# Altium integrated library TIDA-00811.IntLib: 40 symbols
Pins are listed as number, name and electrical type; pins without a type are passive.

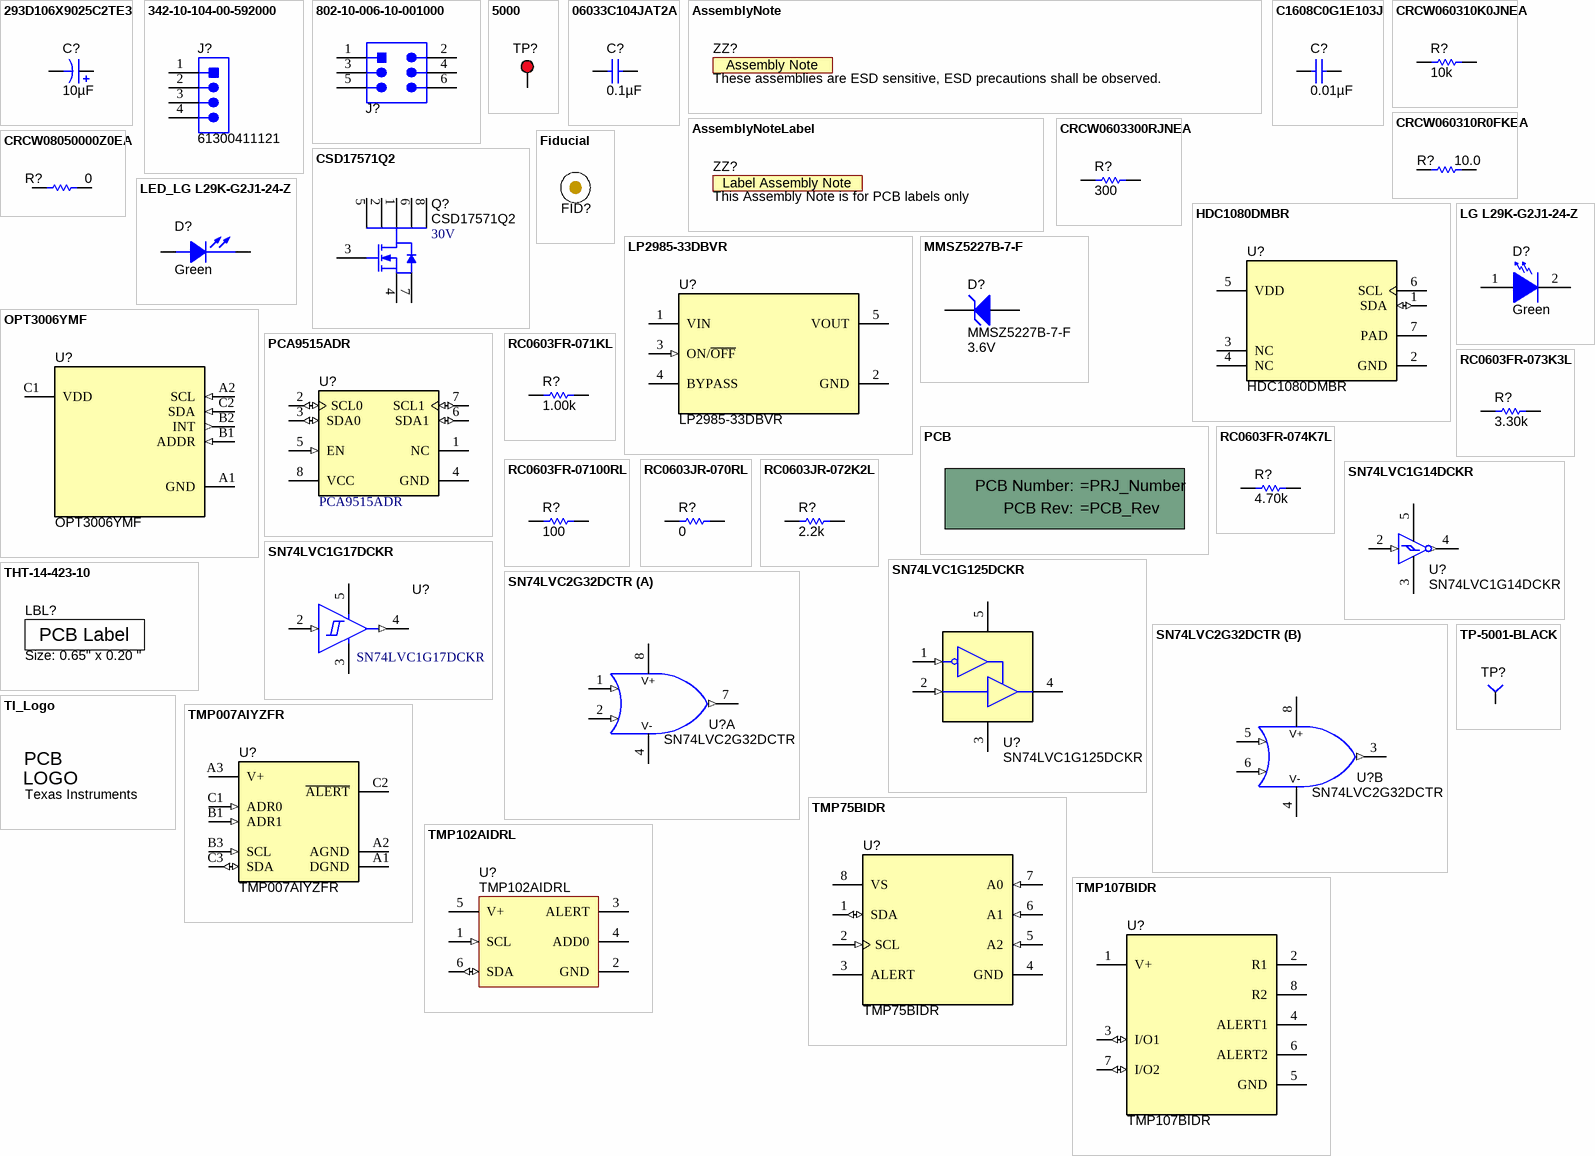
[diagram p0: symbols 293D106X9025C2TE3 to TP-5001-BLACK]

## 293D106X9025C2TE3
designator C?  ValueDisplayed: 10µF  (hidden comment: 293D106X9025C2TE3)
CAP, TA, 10 µF, 25 V, +/- 10%, 1.5 ohm, SMD; Manufacturer: Vishay-Sprague; Polarized: Y; CompType: Capacitor; Value: 10uF; U/M: EA; Cap_F: 0.00001; Tolerance_%: 10; Value1: 1.5 ohm; VDC_V: 25; Value2: 25V; ESR_ohm: 1.5; IRMS_A: 0.27; TaMin_C: -55; TaMax_C: 125; Cap_Case: C; AEC Category: Q200
signal-integrity model Cap
simulation model Cap
footprint 6032-28 (Medium Density IPC based on Vishay Sprague 293D datasheet.)
pins: 1 +, 2 -

## 342-10-104-00-592000
designator J?, comment 61300411121
Header, 2.54mm, 4x1, Gold, TH; Manufacturer: Mill-Max; SymbolCreator: a0412235; Pitch_mm: 2.54; Gender: Male; Shrouded: N; Row_Count: 1
footprint Mill-Max_342-xx-104-00-592000
pins: 1, 2, 3, 4

## 802-10-006-10-001000
designator J?, comment 61300621121  (value not drawn)
Header, 2.54 mm, 3x2, Gold, TH; Manufacturer: Mill-Max; SymbolCreator: a0412235; Pitch_mm: 2.54; Gender: Male; Shrouded: N; Row_Count: 2
footprint Mill-Max_802-10-006-10-001000
pins: 1, 2, 3, 4, 5, 6

## 5000
designator TP?  (value not drawn)
Test Point, Miniature, Red, TH; Manufacturer: Keystone; CompType: Test Point Loop; ContactFinish: Silver
footprint Keystone5000
pins: 1

## 06033C104JAT2A
designator C?  ValueDisplayed: 0.1µF  (hidden comment: 06033C104JAT2A)
CAP, CERM, 0.1 µF, 25 V, +/- 5%, X7R, 0603; Manufacturer: AVX; Polarized: N; CompType: Capacitor; Value: 0.1uF; U/M: EA; Cap_F: 0.0000001; Tolerance_%: 5; ESR_ohm: 0.05; Value1: 0.05 ohm; VDC_V: 25; Value2: 25V; TaMin_C: -55; TaMax_C: 125; Cap_Case: 0603; AEC Category: Q200
signal-integrity model Cap
simulation model Cap
footprint 0603
footprint 0603M
footprint 0603L
footprint 0603_HV
footprint 0603S
pins: 1, 2

## AssemblyNote
designator ZZ?, comment These assemblies are ESD sensitive, ESD precautions shall be observed.  (no BOM)
SymbolCreator: codlsc; CompType: AssemblyNote
footprint AssemblyNote

## AssemblyNoteLabel
designator ZZ?, comment This Assembly Note is for PCB labels only  (no BOM)
SymbolCreator: a0412235
footprint AssemblyNoteLabel

## C1608C0G1E103J
designator C?  ValueDisplayed: 0.01µF  (hidden comment: C1608C0G1E103J)
CAP, CERM, 0.01 µF, 25 V, +/- 5%, C0G/NP0, 0603; Manufacturer: TDK; Polarized: N; CompType: Capacitor; Value: 0.01uF; U/M: EA; Cap_F: 0.00000001; Tolerance_%: 5; Value1: Unknown; VDC_V: 25; Value2: 25V; TaMin_C: -55; TaMax_C: 125; Cap_Case: 0603; AEC Category: Q200
signal-integrity model Cap
simulation model Cap
footprint 0603
footprint 0603M
footprint 0603L
footprint 0603_HV
footprint 0603S
pins: 1, 2

## CRCW060310K0JNEA
designator R?  ValueDisplayed: 10k  (hidden comment: CRCW060310K0JNEA)
RES, 10 k, 5%, 0.1 W, 0603; Manufacturer: Vishay-Dale; CompType: Resistor; Value: 10k; Res_ohm: 10000; Value_Code: 10k0; Tolerance_%: 5; Power_W: 0.1; Value2: 0.1W; VDC_V: 75; TempCo: 200 ppm/C; SizeArea_mm2: 1.28; SizeX_mm: 1.6; SizeY_mm: 0.8; SizeZ_mm: 1; EIA_Code: E24; U/M: EA; AEC Category: Q200
signal-integrity model Resistor
simulation model Resistor
footprint 0603
footprint 0603M
footprint 0603L
footprint 0603_HV
footprint 0603S
pins: 1, 2

## CRCW060310R0FKEA
designator R?  ValueDisplayed: 10.0  (hidden comment: CRCW060310R0FKEA)
RES, 10.0, 1%, 0.1 W, 0603; Manufacturer: Vishay-Dale; CompType: Resistor; Value: 10.0; Res_ohm: 10; Value_Code: 10R0; Tolerance_%: 1; Power_W: 0.1; Value2: 0.1W; VDC_V: 75; TempCo: 100 ppm/C; SizeArea_mm2: 1.28; SizeX_mm: 1.6; SizeY_mm: 0.8; EIA_Code: E96; U/M: EA; AEC Category: Q200
signal-integrity model Resistor
simulation model Resistor
footprint 0603
footprint 0603M
footprint 0603L
footprint 0603_HV
footprint 0603S
pins: 1, 2

## CRCW0603300RJNEA
designator R?  value 300  (hidden comment: CRCW0603300RJNEA)
RES, 300 ohm, 5%, 0.1W, 0603; Manufacturer: Vishay-Dale; CompType: Resistor; Value_Code: 300R; Tolerance_%: 5; Power_W: 0.1; VDC_V: 75; TempCo: 200 ppm/C; EIA_Code: E24; U/M: EA
signal-integrity model Resistor
simulation model Resistor
footprint 0603 (0603 from SM-752 data)
footprint 0603M
footprint 0603L
footprint 0603_HV
footprint 0603
footprint 0603_HV
footprint 0603L
footprint 0603M
simulation model Resistor
signal-integrity model Resistor
pins: 1, 2

## CRCW08050000Z0EA
designator R?  ValueDisplayed: 0  (hidden comment: CRCW08050000Z0EA)
RES, 0, 5%, 0.125 W, 0805; Manufacturer: Vishay-Dale; CompType: Resistor; Value: 0; Value_Code: 0000; Tolerance_%: 5; Power_W: 0.125; Value2: 0.125W; VDC_V: 150; TempCo: 200 ppm/C; SizeArea_mm2: 2.5; SizeX_mm: 2; SizeY_mm: 1.25; SizeZ_mm: 1.45; EIA_Code: E24; U/M: EA; AEC Category: Q200
signal-integrity model Resistor
simulation model Resistor
footprint 0805_HV
footprint 0805_HV1
footprint 0805
footprint 0805M
footprint 0805L
pins: 1, 2

## CSD17571Q2
designator Q?  value 30V
MOSFET, N-CH, 30V, 22A, SON 2X2 MM; Manufacturer: TEXAS INSTRUMENTS; CompType: POWER MOSFET
footprint SON_CSD17571Q2 (SON, MOSFET, N-CH, 30V, 22A, SON 2X2 MM)
pins: 1 D, 2 D, 3 G, 4 S, 5 D, 6 D, 7 S, 8 D

## Fiducial
designator FID?  (value not drawn)
Fiducial mark.  There is nothing to buy or mount.; SymbolCreator: codlsc
footprint Fiducial10-30
footprint Fiducial10-20
footprint Fiducial15-30
footprint Fiducial20-40
footprint Fiducial6.4-20

## HDC1080DMBR
designator U?
Low Power, High Accuracy Digital Humidity Sensor with Temperature Sensor, DMB0006A; Alternate PartNumber: HDC1080DMBT; Manufacturer: Texas Instruments; SymbolCreator: a0411947; CompType: IC; U/M: EA
footprint DMB0006A (TI)
footprint DMB0006A_NV
pins: 1 SDA (io), 2 GND (power), 3 NC, 4 NC, 5 VDD (power), 6 SCL (oc), 7 PAD (power)

## LED_LG L29K-G2J1-24-Z
designator D?  value Green  (hidden comment: LED_LG L29K-G2J1-24-Z)
LED SmartLED Green 570NM; Manufacturer: OSRAM; SymbolCreator: x0120606
footprint LED0603AA
pins: 1 C, 2 A

## LG L29K-G2J1-24-Z
designator D?  value Green  (hidden comment: LG L29K-G2J1-24-Z)
LED, Green, SMD; Manufacturer: OSRAM; Vf_V: 1.7; Value2: 1.7V; Io_A: 0.002; Tjmax_C: 110; Value1: W; U/M: EA
signal-integrity model Diode
footprint LG L29K_GREEN
pins: 1 A, 2 K

## LP2985-33DBVR
designator U?
100-mA ULTRA-LOW DROPOUT REGULATOR WITH SHUTDOWN, DBV0005A; Alternate PartNumber: LP2985-33DBVT; Manufacturer: Texas Instruments; SymbolCreator: Altium; CompType: IC; U/M: EA
footprint DBV0005A_N (SOT23, 5-Leads, Body 2.9x1.6mm, Pitch 0.95mm, Lead Span 2.8mm, IPC Medium Density)
footprint DBV0005A_M
footprint DBV0005A_L
pins: 1 VIN (power), 2 GND (power), 3 ON/~{OFF} (in), 4 BYPASS, 5 VOUT (power)

## MMSZ5227B-7-F
designator D?  value 3.6V
Diode, Zener, 3.6 V, 500 mW, SOD-123; Manufacturer: Diodes Inc.; SymbolCreator: a0412235; U/M: EA; Power_W: 0.5; Vz_V: 3.6; Value1: 0.5W; RJA_CperW: 350; AEC Category: Q101
signal-integrity model Diode
footprint SOD-123
pins: 1 K, 2 A

## OPT3006YMF
designator U?
Ambient Light Sensor, YMF0006A (PICOSTAR-6); Manufacturer: Texas Instruments; SymbolCreator: a0411947; SizeArea_mm2: 0.809776; SizeAreaWB_mm2: 3.611776; SizeX_mm: 0.856; SizeY_mm: 0.946; SizeZ_mm: 0.226; CompType: IC; U/M: EA
footprint YMF0006A
pins: A1 GND (power), A2 SCL (in), B1 ADDR (in), B2 INT (out), C1 VDD (power), C2 SDA (in)

## PCA9515ADR
designator U?
Dual Bidirectional I2C Bus and SMBus Repeater, 2 Channel Width, 2.3 to 3.6 V, -40 to 85 degC, 8-pin SOIC (D), Green (RoHS & no Sb/Br); Manufacturer: Texas Instruments; Alternate PartNumber: Equivalent; SubFamily: I2C Hub, Buffer, Repeater; No. of Outputs: 2; VCC(Max)(V): 3.6; VCC(Min)(V): 2.3; Max Frequency(kHz): 400; Vcc range(V): 2.3 to 5.5; 5V Tolerant I/O: Yes
footprint D0008A_N (SOIC, 8-Leads, Body 4.9x3.9mm, Pitch 1.27mm, IPC Medium Density)
footprint D0008A_L (SOIC, 8-Leads, Body 4.9x3.9mm, Pitch 1.27mm, IPC High Density)
footprint D0008A_M (SOIC, 8-Leads, Body 4.9x3.9mm, Pitch 1.27mm, IPC Low Density)
pins: 1 NC "No internal connection", 2 SCL0 (io) "Serial clock bus 0", 3 SDA0 (io) "Serial data bus 0", 4 GND (power) "Supply ground", 5 EN (in) "Active-high repeater enable input", 6 SDA1 (io) "Serial data bus 1", 7 SCL1 (io) "Serial clock bus 1", 8 VCC (power) "Supply power"

## PCB
designator !PCB?, comment Printed Circuit Board  (value not drawn)  (mechanical)
Manufacturer: Any; SymbolCreator: a0412235; CompType: PCB
1 alternate drawing of the same symbol

## RC0603FR-071KL
designator R?  ValueDisplayed: 1.00k  (hidden comment: RC0603FR-071KL)
RES, 1.00 k, 1%, 0.1 W, 0603; Manufacturer: Yageo America; CompType: Resistor; Value: 1.00k; Res_ohm: 1000; Value_Code: 1k00; Tolerance_%: 1; Power_W: 0.1; Value2: 0.1W; VDC_V: 150; TempCo: 200 ppm/C; EIA_Code: E96; U/M: EA; AEC Category: Q200
signal-integrity model Resistor
simulation model Resistor
footprint 0603
footprint 0603M
footprint 0603L
footprint 0603_HV
footprint 0603S
pins: 1, 2

## RC0603FR-073K3L
designator R?  ValueDisplayed: 3.30k  (hidden comment: RC0603FR-073K3L)
RES, 3.30 k, 1%, 0.1 W, 0603; Manufacturer: Yageo America; CompType: Resistor; Value: 3.30k; Res_ohm: 3300; Value_Code: 3k30; Tolerance_%: 1; Power_W: 0.1; Value2: 0.1W; VDC_V: 150; TempCo: 200 ppm/C; U/M: EA; AEC Category: Q200
signal-integrity model Resistor
simulation model Resistor
footprint 0603
footprint 0603M
footprint 0603L
footprint 0603_HV
footprint 0603S
pins: 1, 2

## RC0603FR-074K7L
designator R?  ValueDisplayed: 4.70k  (hidden comment: RC0603FR-074K7L)
RES, 4.70 k, 1%, 0.1 W, 0603; Manufacturer: Yageo America; CompType: Resistor; Value: 4.70k; Res_ohm: 4700; Value_Code: 4k70; Tolerance_%: 1; Power_W: 0.1; Value2: 0.1W; VDC_V: 150; TempCo: 200 ppm/C; U/M: EA; AEC Category: Q200
signal-integrity model Resistor
simulation model Resistor
footprint 0603
footprint 0603M
footprint 0603L
footprint 0603_HV
footprint 0603S
pins: 1, 2

## RC0603FR-07100RL
designator R?  ValueDisplayed: 100  (hidden comment: RC0603FR-07100RL)
RES, 100, 1%, 0.1 W, 0603; Manufacturer: Yageo America; CompType: Resistor; Value: 100; Value_Code: 100R; Tolerance_%: 1; Power_W: 0.1; Value2: 0.1W; VDC_V: 150; TempCo: 200 ppm/C; EIA_Code: E96; U/M: EA; AEC Category: Q200
signal-integrity model Resistor
simulation model Resistor
footprint 0603
footprint 0603M
footprint 0603L
footprint 0603_HV
footprint 0603S
pins: 1, 2

## RC0603JR-070RL
designator R?  ValueDisplayed: 0  (hidden comment: RC0603JR-070RL)
RES, 0, 5%, 0.1 W, 0603; Manufacturer: Yageo America; CompType: Resistor; Value: 0; Value_Code: 0000; Tolerance_%: 5; Power_W: 0.1; Value2: 0.1W; VDC_V: 50; TempCo: 200 ppm/C; SizeArea_mm2: 1.28; SizeX_mm: 1.6; SizeY_mm: 0.8; SizeZ_mm: 1; EIA_Code: E24; U/M: EA; AEC Category: Q200
signal-integrity model Resistor
simulation model Resistor
footprint 0603
footprint 0603M
footprint 0603L
footprint 0603_HV
footprint 0603S
pins: 1, 2

## RC0603JR-072K2L
designator R?  ValueDisplayed: 2.2k  (hidden comment: RC0603JR-072K2L)
RES, 2.2 k, 5%, 0.1 W, 0603; Manufacturer: Yageo America; CompType: Resistor; Value: 2.2k; Res_ohm: 2200; Value_Code: 2k20; Tolerance_%: 5; Power_W: 0.1; Value2: 0.1W; VDC_V: 50; TempCo: 100 ppm/C; SizeArea_mm2: 1.28; SizeX_mm: 1.6; SizeY_mm: 0.8; SizeZ_mm: 1; EIA_Code: E24; U/M: EA; AEC Category: Q200
signal-integrity model Resistor
simulation model Resistor
footprint 0603
footprint 0603M
footprint 0603L
footprint 0603_HV
footprint 0603S
pins: 1, 2

## SN74LVC1G14DCKR
designator U?
SINGLE SCHMITT-TRIGGER INVERTER, DCK0005A; Alternate PartNumber: SN74LVC1G14DCKT; Manufacturer: Texas Instruments; SymbolCreator: a0799628; CompType: IC; U/M: EA
footprint DCK0005A_N
footprint DCK0005A_M
footprint DCK0005A_L
pins: 2 A (in), 3 GND (power), 4 Y (out), 5 VCC (power)

## SN74LVC1G17DCKR
designator U?
SINGLE SCHMITT-TRIGGER BUFFER, DCK0005A (SOT-5); Alternate PartNumber: SN74LVC1G17DCKT; Manufacturer: Texas Instruments; SymbolCreator: a0799628; SizeArea_mm2: 4.2; SizeAreaWB_mm2: 9.3; SizeX_mm: 2.1; SizeY_mm: 2; SizeZ_mm: 1.1; CompType: IC; U/M: EA
footprint DCK0005A_N
footprint DCK0005A_M
footprint DCK0005A_L
pins: 2 A (in), 3 GND (power), 4 Y (out), 5 VCC (power)

## SN74LVC1G125DCKR
designator U?
Single Bus Buffer Gate With 3-State Output, DCK0005A; Alternate PartNumber: SN74LVC1G125DCKT; Manufacturer: Texas Instruments; SymbolCreator: Altium; CompType: IC; U/M: EA
footprint DCK0005A_N (SOT353, 5-Leads, Body 2x1.3mm, Pitch 0.65mm, Lead Span 2.1mm, IPC Medium Density)
footprint DCK0005A_M
footprint DCK0005A_L
pins: 1 ~{OE} (in), 2 A (in), 3 GND (power), 4 Y (hiz), 5 VCC (power)

## SN74LVC2G32DCTR
designator U?
Dual 2-Input Positive-OR Gate, DCT0008A; Manufacturer: Texas Instruments; SymbolCreator: a0411947; CompType: IC; U/M: EA
footprint DCT0008A_N
footprint DCT0008A_M
footprint DCT0008A_L
pins on every part: 4 GND (power), 8 VCC (power)
part A pins: 1 1A (in), 2 1B (in), 7 1Y (out)
part B pins: 3 2Y (out), 5 2A (in), 6 2B (in)

## THT-14-423-10
designator LBL?, comment Size: 0.65" x 0.20 "
Thermal Transfer Printable Labels, 0.650" W x 0.200" H - 10,000 per roll; Manufacturer: Brady; PartNumber: THT-14-423-10; SymbolCreator: a0412235; CompType: Label
footprint Label_650x200

## TI_Logo
designator Logo?, comment Texas Instruments  (no BOM)
Texas Instrument Corporate Signature; SymbolCreator: codlsc
footprint TI_Stacked_SolderMask_Medium
footprint TI_Stacked_SolderMask_Small
footprint TI_Stacked_Overlay_Medium
footprint TI_Stacked_Overlay_Small
footprint TI_Horizontal_SolderMask_Medium
footprint TI_Horizontal_SolderMask_Small
footprint TI_Horizontal_Overlay_Medium
footprint TI_Horizontal_Overlay_Small
footprint TI_Symbol_SolderMask_Small
footprint TI_Symbol_Overlay_Medium
footprint TI_Symbol_Overlay_Small
footprint TI_Symbol_SolderMask_Medium

## TMP007AIYZFR
designator U?
Infrared Thermopile Sensor with Integrated Math Engine, YZF0008AEAE; Alternate PartNumber: TMP007AIYZFT; Manufacturer: Texas Instruments; SymbolCreator: a0411947; SizeArea_mm2: 2.359296; SizeAreaWB_mm2: 6.431296; SizeX_mm: 1.536; SizeZ_mm: 0.625; CompType: IC; U/M: EA
footprint YZF0008AEAE
pins: A1 DGND (power), A2 AGND (power), A3 V+ (power), B1 ADR1 (in), B3 SCL (in), C1 ADR0 (in), C2 ~{ALERT} (oc), C3 SDA (io)

## TMP75BIDR
designator U?
1.4V-Capable Temperature Sensor with I2C/SMBus Interface in LM75 Form Factor & Pinout, D0008A (SOIC-8); Manufacturer: Texas Instruments; SymbolCreator: a0411947; SizeArea_mm2: 30.38; SizeAreaWB_mm2: 56.58; SizeX_mm: 4.9; SizeY_mm: 6.2; SizeZ_mm: 1.75; CompType: IC; U/M: EA
footprint D0008A_N
footprint D0008A_M
footprint D0008A_L
pins: 1 SDA (io), 2 SCL (in), 3 ALERT (oc), 4 GND (power), 5 A2 (in), 6 A1 (in), 7 A0 (in), 8 VS (power)

## TMP102AIDRL
designator U?
Low Power Digital Temperature Sensor With SMBus/Two-Wire Serial Interface in SOT563, DRL0006A; Alternate Manufacturer: None; Manufacturer: Texas Instruments; SymbolCreator: a0411947; CompType: IC; U/M: EA
footprint DRL0006A_N (SOTFL, 6-Flat Leads, Body 1.2x1.6x0.6mm, Pitch 0.5mm, IPC Medium Density)
footprint DRL0006A_M
footprint DRL0006A_L
pins: 1 SCL (in), 2 GND (power), 3 ALERT (oc), 4 ADD0, 5 V+ (power), 6 SDA (io)

## TMP107BIDR
designator U?
TMP107B, D0008A; Manufacturer: Texas Instruments; SymbolCreator: Altium; CompType: IC; U/M: EA
footprint D0008A_N (SOIC, 8-Leads, Body 4.9x3.9mm, Pitch 1.27mm, IPC Medium Density)
footprint D0008A_M
footprint D0008A_L
pins: 1 V+ (power), 2 R1, 3 I/O1 (io), 4 ALERT1, 5 GND (power), 6 ALERT2, 7 I/O2 (io), 8 R2

## TP-5001-BLACK
designator TP?  (value not drawn)
Test Point,  Black, Thru Hole Color Keyed; Manufacturer: Keystone; PartNumber: 5001; area: 10.000; Value: 5001
footprint TH-40
pins: 1

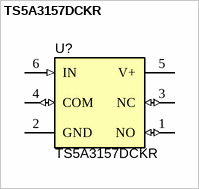
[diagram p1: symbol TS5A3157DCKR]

## TS5A3157DCKR
designator U?
10-OHM SPDT ANALOG SWITCH, DCK0006A (SOT-SC70-6); Manufacturer: Texas Instruments; SymbolCreator: a0411947; SizeArea_mm2: 4.2; SizeAreaWB_mm2: 9.3; SizeX_mm: 2.1; SizeY_mm: 2; SizeZ_mm: 1.1; CompType: IC; U/M: EA
footprint DCK0006A_N
footprint DCK0006A_M
footprint DCK0006A_L
pins: 1 NO (io), 2 GND (power), 3 NC (io), 4 COM (io), 5 V+ (power), 6 IN (in)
